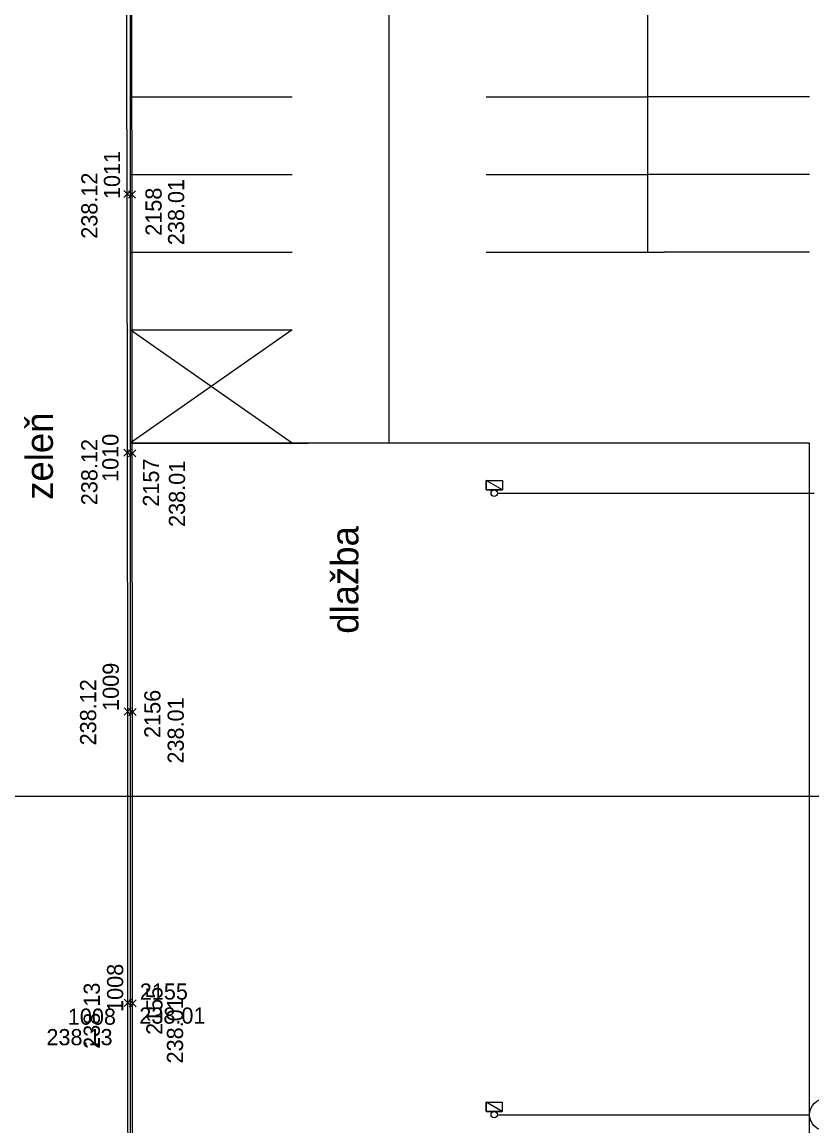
# Model space of a CAD drawing. Extents: x -264205 to -263659, y -1242401 to -1241986.
# Drawn here: x -263951.44 to -263927.02, y -1242155.1 to -1242121 of the extents above; entities that cross this region are included whole.
import ezdxf

# ---------------------------------------------------------------- set-up
doc = ezdxf.new("R2010")
doc.units = 0
for name, color, linetype in [('BOD_CISLO_2-1', 7, 'Continuous'), ('BOD_CISLO_2-3', 7, 'Continuous'), ('BOD_SYMBOL_2-1', 7, 'Continuous'), ('BOD_SYMBOL_2-3', 7, 'Continuous'), ('BOD_VYSKA_2-1', 7, 'Continuous'), ('BOD_VYSKA_2-3', 7, 'Continuous'), ('POPIS_2-3', 7, 'Continuous'), ('PROJEKT_OBRUBNIKY_KOMUNIKACIE', 7, 'Continuous'), ('PROJEKT_TDZ_VODOROVNE', 7, 'Continuous'), ('RAM_NA_TLAC_2-1_1-250', 7, 'Continuous'), ('SITUACIA_DSP_2D', 7, 'Continuous'), ('SO_20-4_OBRUBNIKY_DOLNA_HRANA', 7, 'Continuous'), ('SO_20-4_OBRUBNIKY_HORNA_HRANA', 7, 'Continuous')]:
    doc.layers.add(name, color=color, linetype=linetype)

msp = doc.modelspace()

# ---------------------------------------------------------------- linework, layer by layer
at = {"layer": 'BOD_SYMBOL_2-1'}
for p, q in [((-263948.279, -1242151.407), (-263948.057, -1242151.186)), ((-263948.057, -1242151.407), (-263948.279, -1242151.186)), ((-263948.132, -1242151.424), (-263947.91, -1242151.203)), ((-263947.91, -1242151.424), (-263948.132, -1242151.203))]:
    msp.add_line(p, q, dxfattribs=at)
at = {"layer": 'BOD_SYMBOL_2-3'}
for p, q in [((-263948.077, -1242126.417), (-263948.297, -1242126.195)), ((-263948.077, -1242126.195), (-263948.297, -1242126.417)), ((-263947.93, -1242126.434), (-263948.15, -1242126.213)), ((-263947.93, -1242126.213), (-263948.15, -1242126.434)), ((-263948.069, -1242134.411), (-263948.291, -1242134.191)), ((-263948.069, -1242134.191), (-263948.291, -1242134.411)), ((-263947.922, -1242134.428), (-263948.144, -1242134.208)), ((-263947.922, -1242134.208), (-263948.144, -1242134.428)), ((-263948.062, -1242142.406), (-263948.283, -1242142.184)), ((-263948.062, -1242142.184), (-263948.283, -1242142.406)), ((-263947.915, -1242142.423), (-263948.136, -1242142.201)), ((-263947.915, -1242142.201), (-263948.136, -1242142.423)), ((-263948.057, -1242151.407), (-263948.279, -1242151.186)), ((-263948.057, -1242151.186), (-263948.279, -1242151.407)), ((-263947.91, -1242151.424), (-263948.132, -1242151.203)), ((-263947.91, -1242151.203), (-263948.132, -1242151.424))]:
    msp.add_line(p, q, dxfattribs=at)
at = {"layer": 'PROJEKT_OBRUBNIKY_KOMUNIKACIE'}
msp.add_line((-263948.093, -1242087.901), (-263948.093, -1242241.458), dxfattribs=at)
at = {"layer": 'PROJEKT_TDZ_VODOROVNE'}
for p, q in [((-263940.091, -1242134.007), (-263940.093, -1242087.307)), ((-263932.093, -1242128.107), (-263932.093, -1242087.307)), ((-263948.093, -1242123.307), (-263943.093, -1242123.307)), ((-263937.093, -1242123.307), (-263932.093, -1242123.307)), ((-263927.093, -1242123.307), (-263932.093, -1242123.307)), ((-263948.093, -1242125.707), (-263943.093, -1242125.707)), ((-263937.093, -1242125.707), (-263932.093, -1242125.707)), ((-263927.093, -1242125.707), (-263932.093, -1242125.707)), ((-263948.093, -1242128.107), (-263943.093, -1242128.107)), ((-263937.093, -1242128.107), (-263931.593, -1242128.107)), ((-263927.093, -1242128.107), (-263931.593, -1242128.107)), ((-263948.093, -1242130.507), (-263943.093, -1242130.507)), ((-263943.093, -1242130.507), (-263948.093, -1242134.007)), ((-263943.093, -1242134.007), (-263948.093, -1242130.507)), ((-263948.093, -1242134.007), (-263942.593, -1242134.007))]:
    msp.add_line(p, q, dxfattribs=at)
msp.add_lwpolyline([(-263927.093, -1242134.007), (-263948.093, -1242134.007), (-263948.093, -1242184.007), (-263927.093, -1242184.007), (-263927.093, -1242134.007)], dxfattribs=at)
at = {"layer": 'RAM_NA_TLAC_2-1_1-250'}
msp.add_lwpolyline([(-264147.913, -1242144.907), (-263857.913, -1242144.907), (-263857.913, -1242219.157), (-264147.913, -1242219.157)], close=True, dxfattribs=at)
at = {"layer": 'SITUACIA_DSP_2D'}
for p, q in [((-263948.093, -1242087.901), (-263948.093, -1242241.458)), ((-263937.092, -1242135.452), (-263937.092, -1242135.162)), ((-263937.092, -1242135.162), (-263936.592, -1242135.162)), ((-263936.592, -1242135.452), (-263937.092, -1242135.162)), ((-263936.592, -1242135.452), (-263937.092, -1242135.162)), ((-263937.092, -1242135.162), (-263937.092, -1242135.452)), ((-263936.592, -1242135.162), (-263936.592, -1242135.452)), ((-263936.592, -1242135.452), (-263937.092, -1242135.452)), ((-263937.092, -1242135.452), (-263936.592, -1242135.452)), ((-263936.743, -1242135.552), (-263926.953, -1242135.552)), ((-263937.093, -1242154.652), (-263937.093, -1242154.362)), ((-263937.093, -1242154.362), (-263936.593, -1242154.362)), ((-263936.593, -1242154.652), (-263937.093, -1242154.362)), ((-263936.593, -1242154.652), (-263937.093, -1242154.362)), ((-263937.093, -1242154.362), (-263937.093, -1242154.652)), ((-263936.593, -1242154.362), (-263936.593, -1242154.652)), ((-263936.593, -1242154.652), (-263937.093, -1242154.652)), ((-263937.093, -1242154.652), (-263936.593, -1242154.652)), ((-263936.743, -1242154.752), (-263927.093, -1242154.752))]:
    msp.add_line(p, q, dxfattribs=at)
for centre, radius in [((-263936.843, -1242135.552), 0.1), ((-263926.593, -1242154.752), 0.5), ((-263936.843, -1242154.752), 0.1)]:
    msp.add_circle(centre, radius, dxfattribs=at)
at = {"layer": 'SO_20-4_OBRUBNIKY_DOLNA_HRANA'}
msp.add_lwpolyline([(-263948.011, -1242159.299), (-263948.021, -1242151.313), (-263948.025, -1242142.312), (-263948.033, -1242134.318), (-263948.04, -1242126.323), (-263948.059, -1242118.324), (-263948.067, -1242110.327), (-263948.076, -1242102.327), (-263948.082, -1242094.331), (-263948.087, -1242087.302)], dxfattribs=at)
at = {"layer": 'SO_20-4_OBRUBNIKY_HORNA_HRANA'}
msp.add_lwpolyline([(-263948.158, -1242159.282), (-263948.168, -1242151.296), (-263948.172, -1242142.295), (-263948.18, -1242134.301), (-263948.187, -1242126.306), (-263948.206, -1242118.307), (-263948.214, -1242110.31), (-263948.223, -1242102.31), (-263948.229, -1242094.314), (-263948.234, -1242087.448)], dxfattribs=at)

# ---------------------------------------------------------------- texts
at = {"layer": 'BOD_CISLO_2-1'}
for s, p in [('2155', (-263947.8, -1242151.197)), ('1008', (-263950.025, -1242151.973))]:
    msp.add_text(s, height=0.5, dxfattribs=at).set_placement(p)
at = {"layer": 'BOD_CISLO_2-3'}
for s, p in [('1011', (-263948.411, -1242126.464)), ('2158', (-263947.124, -1242127.599)), ('1010', (-263948.459, -1242135.203)), ('2157', (-263947.205, -1242135.967)), ('1009', (-263948.447, -1242142.277)), ('2156', (-263947.161, -1242143.114)), ('1008', (-263948.313, -1242151.578)), ('2155', (-263947.099, -1242152.286))]:
    msp.add_text(s, height=0.5, rotation=90, dxfattribs=at).set_placement(p)
at = {"layer": 'BOD_VYSKA_2-1'}
for s, p in [('238.01', (-263947.815, -1242151.94)), ('238.13', (-263950.686, -1242152.606))]:
    msp.add_text(s, height=0.5, dxfattribs=at).set_placement(p)
at = {"layer": 'BOD_VYSKA_2-3'}
for s, p in [('238.12', (-263949.108, -1242127.691)), ('238.01', (-263946.427, -1242127.889)), ('238.12', (-263949.11, -1242135.923)), ('238.01', (-263946.401, -1242136.594)), ('238.12', (-263949.147, -1242143.343)), ('238.01', (-263946.439, -1242143.905)), ('238.13', (-263949.034, -1242152.718)), ('238.01', (-263946.462, -1242153.17))]:
    msp.add_text(s, height=0.5, rotation=90, dxfattribs=at).set_placement(p)
at = {"layer": 'POPIS_2-3'}
for s, p in [('zeleň', (-263950.485, -1242135.757)), ('dlažba', (-263941.041, -1242139.894))]:
    msp.add_text(s, height=0.8438, rotation=90, dxfattribs=at).set_placement(p)

doc.saveas('drawing.dxf')
